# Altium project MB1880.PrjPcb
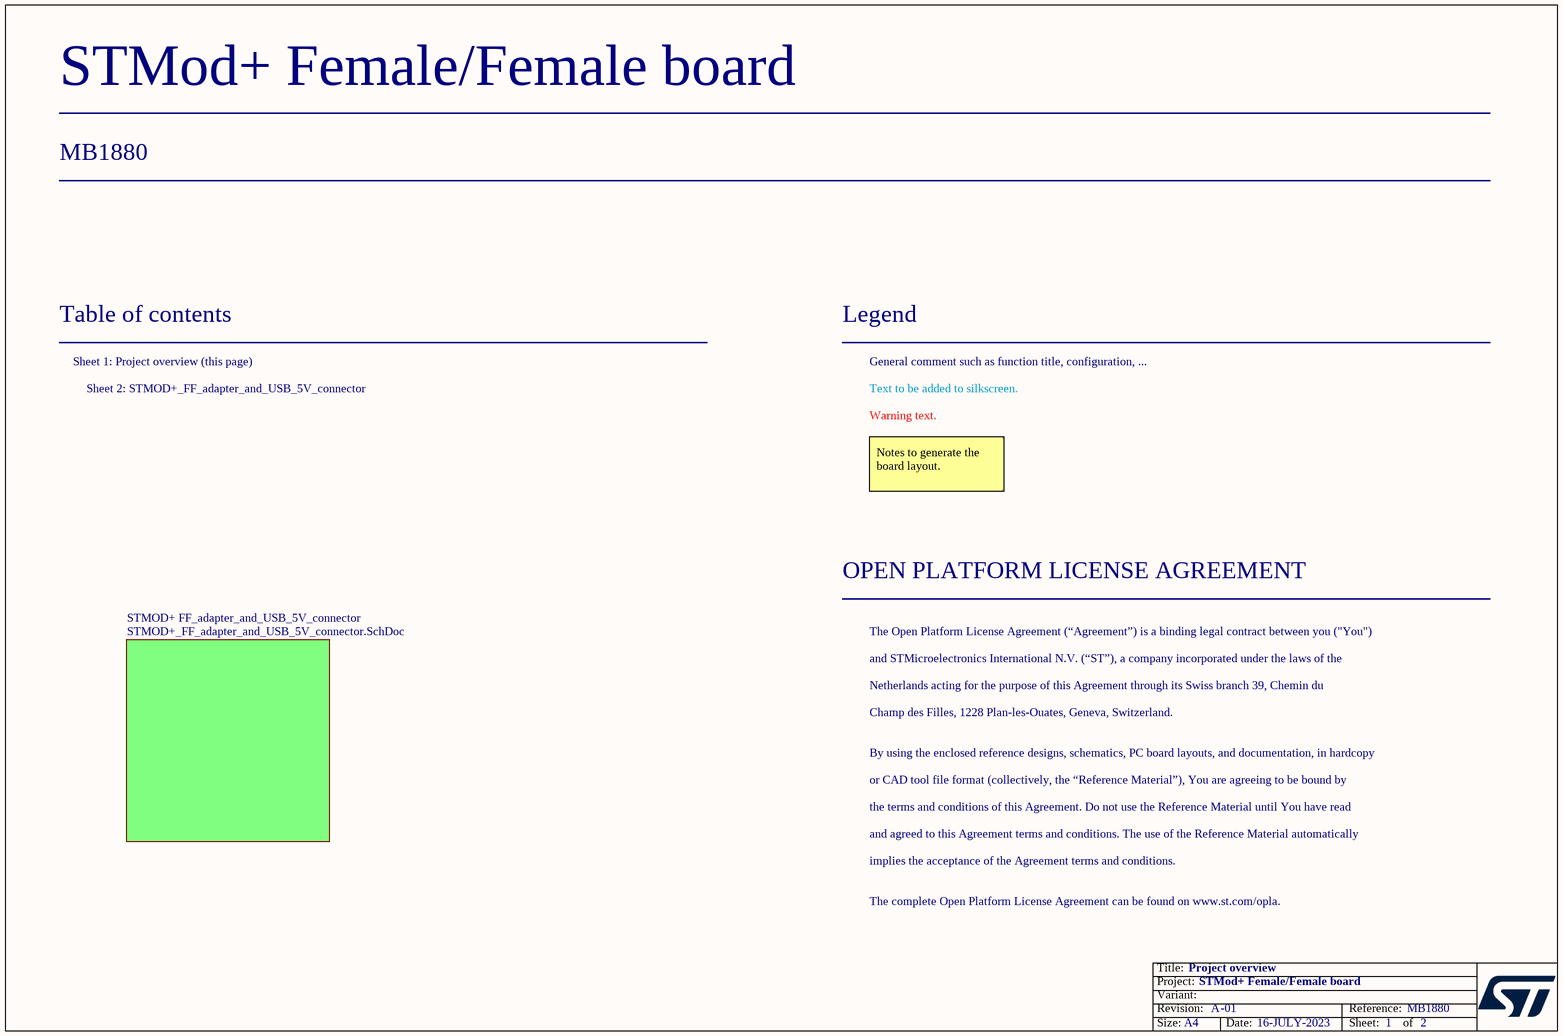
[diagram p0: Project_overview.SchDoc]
Board_Reference: MB1880; Board_PCB_Revision: A; Board_Name: STMod+ Female/Female board; Board_Document_Date: 16-JULY-2023; Board_Assembly_Revision: 01
2 sheets, 14 parts. Net scope: global (net labels, ports and power ports of the same name join across sheets).
Board file: MB1880.PcbDoc
Sheets:
  Project_overview.SchDoc
    STMOD+ FF_adapter_and_USB_5V_connector = STMOD+_FF_adapter_and_USB_5V_connector.SchDoc

## Sheet Project_overview.SchDoc: Project overview
size A4; Date: Not used; ApprovedBy: Not used; CheckedBy: Not used; Author: Not used; CompanyName: STMicroelectronics; DrawnBy: Not used; Engineer: Not used; Organization: Not used; Address1: Not used; Address2: Not used; Address3: Not used; Address4: Not used; DocumentNumber: Not used; Revision: Not used; SheetNumber: 1; SheetTotal: 2

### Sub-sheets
STMOD+ FF_adapter_and_USB_5V_connector = STMOD+_FF_adapter_and_USB_5V_connector.SchDoc: no entries

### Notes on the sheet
- Table of contents
- Sheet 1: Project overview (this page)
- Legend
- General comment such as function title, configuration, ...
- Sheet 2: STMOD+_FF_adapter_and_USB_5V_connector
- Text to be added to silkscreen.
- Warning text.
- Notes to generate the board layout.
- OPEN PLATFORM LICENSE AGREEMENT
- The Open Platform License Agreement (“Agreement”) is a binding legal contract between you ("You")
- and STMicroelectronics International N.V. (“ST”), a company incorporated under the laws of the
- Netherlands acting for the purpose of this Agreement through its Swiss branch 39, Chemin du
- Champ des Filles, 1228 Plan-les-Ouates, Geneva, Switzerland.
- By using the enclosed reference designs, schematics, PC board layouts, and documentation, in hardcopy
- or CAD tool file format (collectively, the “Reference Material”), You are agreeing to be bound by
- the terms and conditions of this Agreement. Do not use the Reference Material until You have read
- and agreed to this Agreement terms and conditions. The use of the Reference Material automatically
- implies the acceptance of the Agreement terms and conditions.
- The complete Open Platform License Agreement can be found on www.st.com/opla.

## Sheet STMOD+_FF_adapter_and_USB_5V_connector.SchDoc: STMOD+ FF adapter and USB 5V connector
size A4; Date: Not used; ApprovedBy: Not used; CheckedBy: Not used; Author: Not used; CompanyName: STMicroelectronics; DrawnBy: Not used; Engineer: Not used; Organization: Not used; Address1: Not used; Address2: Not used; Address3: Not used; Address4: Not used; DocumentNumber: Not used; Revision: Not used; SheetNumber: 2; SheetTotal: 2
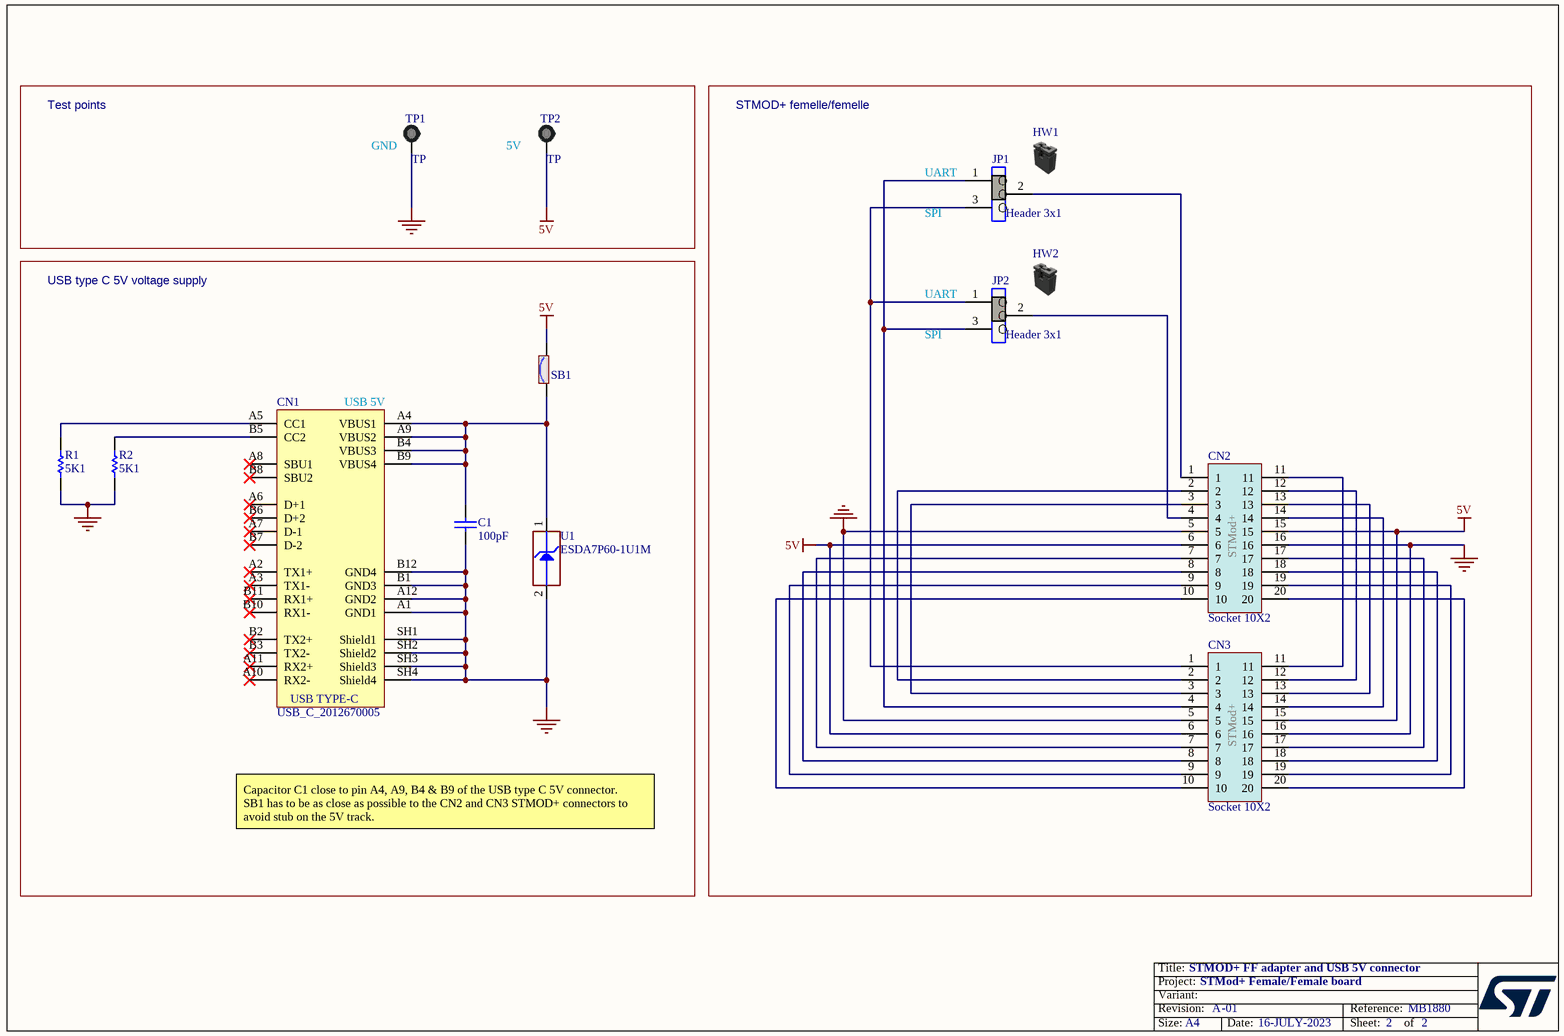
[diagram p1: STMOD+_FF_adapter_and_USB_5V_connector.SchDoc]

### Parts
C1  value 100pF  [C0402]
CN1  value USB_C_2012670005  [CON_USB-TYPEC_MOLEX_2012670005]  (hidden comment: USB_TYPE_C_Receptacle)
CN2  value Socket 10X2  [CON_SAMTEC_SQT-110-01-F-D-RA__STMOD+]  (hidden comment: Socket 10X2 STMod+)
CN3  value Socket 10X2  [CON_SAMTEC_SQT-110-01-F-D-RA__STMOD+]  (hidden comment: Socket 10X2 STMod+)
HW1  (no value)  (mechanical)
HW2  (no value)  (mechanical)
JP1  value Header 3x1  [CON_SAMTEC_TSW-103-07-F-S]  (hidden comment: Jumper_Header 3x1 Fitted 1-2)
JP2  value Header 3x1  [CON_SAMTEC_TSW-103-07-F-S]  (hidden comment: Jumper_Header 3x1 Fitted 1-2)
R1  value 5K1  [R0402]  (hidden comment: Resistor)
R2  value 5K1  [R0402]  (hidden comment: Resistor)
SB1  (no value)  [SOLDER-BRIDGE_R0603-0R]
TP1  value TP  [TP_PTH_1MM_2MM]  (hidden comment: Test_Point_PTH_1mm_2mm)  (no BOM)
TP2  value TP  [TP_PTH_1MM_2MM]  (hidden comment: Test_Point_PTH_1mm_2mm)  (no BOM)
U1  value ESDA7P60-1U1M  [ESD_QFN2_1P6X1_P125]  (hidden comment: ESD-TRANSIL)

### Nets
5V: CN2.6 CN2.15 CN3.6 CN3.15 SB1.2 TP2.1
GND: C1.1 CN1.A1(GND1) CN1.A12(GND2) CN1.B1(GND3) CN1.B12(GND4) CN1.SH1(Shield1) CN1.SH2(Shield2) CN1.SH3(Shield3) CN1.SH4(Shield4) CN2.5 CN2.16 CN3.5 CN3.16 R1.1 R2.1 TP1.1 U1.2(GND)
NetC1_2: C1.2 CN1.A4(VBUS1) CN1.A9(VBUS2) CN1.B4(VBUS3) CN1.B9(VBUS4) SB1.1 U1.1(IO1)
NetCN1_A5: CN1.A5(CC1) R1.2
NetCN1_B5: CN1.B5(CC2) R2.2
NetCN2_1: CN2.1 JP1.2
NetCN2_2: CN2.2 CN3.2
NetCN2_3: CN2.3 CN3.3
NetCN2_4: CN2.4 JP2.2
NetCN2_7: CN2.7 CN3.7
NetCN2_8: CN2.8 CN3.8
NetCN2_9: CN2.9 CN3.9
NetCN2_10: CN2.10 CN3.10
NetCN2_11: CN2.11 CN3.11
NetCN2_12: CN2.12 CN3.12
NetCN2_13: CN2.13 CN3.13
NetCN2_14: CN2.14 CN3.14
NetCN2_17: CN2.17 CN3.17
NetCN2_18: CN2.18 CN3.18
NetCN2_19: CN2.19 CN3.19
NetCN2_20: CN2.20 CN3.20
NetCN3_1: CN3.1 JP1.3 JP2.1
NetCN3_4: CN3.4 JP1.1 JP2.3

Not connected (* = marked no-connect by the designer): CN1 A2(TX1+)* A3(TX1-)* A6(D+1)* A7(D-1)* A8(SBU1)* A10(RX2-)* A11(RX2+)* B2(TX2+)* B3(TX2-)* B6(D+2)* B7(D-2)* B8(SBU2)* B10(RX1-)* B11(RX1+)*

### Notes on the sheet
- Test points
- STMOD+ femelle/femelle
- (near TP1) GND
- (near TP2) 5V
- (near JP1) UART
- (near JP1) SPI
- USB type C 5V voltage supply
- (near JP2) UART
- (near JP2) SPI
- (near CN1) USB 5V
- Capacitor C1 close to pin A4, A9, B4 & B9 of the USB type C 5V connector.
  SB1 has to be as close as possible to the CN2 and CN3 STMOD+ connectors to avoid stub on the 5V track.

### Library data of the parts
C1 = MCD-00205: Capacitor, MLCC, 100pF, 50V, NPO, 5%, 0402, T=0,5mm; Manufacturer_Part_Number: CC0402JRNPO9BN101; Manufacturer: YAGEO; Provided_By: SUBCO; ECCN_US: EAR99; ECCN_EU: NEC
CN1 = MCD-02421: USB_TypeC, 24 pins, RA, SMD, T=3.71mm (USB Certified 3.1); Part_Type: Connector; Part_Preference: Recommended; Manufacturer: MOLEX; Manufacturer_Part_Number: 2012670005; Order_Code_RS: 176-8434; Component_Country_Of_Origin: Unknown
CN2 CN3 = MCD-00309: Socket, 10x2, 2mm, RA, TH, T=6.35mm/2.29mm; Part_Type: Connector; Part_Preference: Recommended; Manufacturer: SAMTEC; Manufacturer_Part_Number: SQT-110-01-F-D-RA; Order_Code_RS: 180-1541; Component_Country_Of_Origin: China, Costa Rica, Malaysia, United States, Vietnam
HW1 HW2 = MCD-00043: SHUNT 2.54mm BLACK; Manufacturer_Part_Number: SNT-100-BK-G; Manufacturer: SAMTEC; Part_Type: Mechanical; Alternate_Manufacturer_Part_Number: 316102S111A; Alternate_Manufacturer: JIUBABA; Provided_By: SUBCO; Value: SNT-100-BK-G
JP1 JP2 = MCD-00684: Header, 3x1, 2.54mm, VR, TH, T=5.84mm/2.54mm; Part_Type: Connector; Part_Preference: Recommended; Manufacturer: SAMTEC; Manufacturer_Part_Number: TSW-103-07-F-S; Order_Code_RS: 161-2248; Component_Country_Of_Origin: China, Costa Rica, Malaysia, United States, Vietnam
R1 R2 = MCD-00333: Resistor, 5K1, 0402, +/-1%, 1/16W; Part_Preference: Recommended; Manufacturer: YAGEO; Manufacturer_Part_Number: RC0402FR-075K1L; Component_Country_Of_Origin: China
SB1 = MCD-00071: Solder Bridge ON; Part_Type: Mechanical; Manufacturer_Part_Number: RC0603JR-070RL; Manufacturer: YAGEO; Provided_By: SUBCO
TP1 TP2 = MCD-01506: Test Point trought hole 1mm/2mm; Part_Type: Misc; Part_Preference: Recommended
U1 = MCD-00251: High power transient voltage suppressor, 7V breakdown; BMS_Part_Number: 9179042; Part_Type: Diode; Part_Preference: Recommended; Manufacturer: STMICROELECTRONICS; Manufacturer_HQ_COO: EU; Component_Country_Of_Origin: China

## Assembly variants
uart: all parts fitted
